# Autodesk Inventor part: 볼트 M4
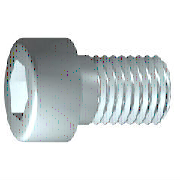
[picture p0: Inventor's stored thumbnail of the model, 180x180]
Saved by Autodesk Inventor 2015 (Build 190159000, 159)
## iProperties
IsCustomPart: 0
Created: 2012-02
Part Number: 볼트 M4
Material: 스테인리스강
Description: 6각 소켓 머리 캡 나사
Document SubType Name: Modeling
Standard: ISO 4762
Designer: mduedu
Standard Revision: Fourth edition 2004-03-01
Standards Organization: ISO
Language: ko-KR
Size Designation: M4 x 12
Categories: <MemberInstance><Categories><Category DisplayName="조임쇠" InternalName="e4da775c-781d-43d5-af7c-5136215cf5a6" Mnemonic="FSTN"><Category DisplayName="볼트" InternalN
Density: 7.75 g/cm^3
Appearance: 반광택
Author: mduedu
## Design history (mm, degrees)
sketch "스케치1"
  geometry: L1 (-1, 0)-(12, 0); L2 (12, 0)-(12, 2); L3 (12, 2)-(1.75, 2); L4 (1.75, 2)-(1.32, 2); L5 (1.32, 2)-(0, 2); L6 (0, 2)-(0, 3.5); L7 (0, 3.5)-(-4, 3.5); L8 (-4, 3.5)-(-4, 1.732); L9 (-4, 1.732)-(-2, 1.732); L10 (-2, 1.732)-(-1, 0); L11 (-7.2, 0)-(15.2, 0) reference; L12 (0, -0.7)-(0, 4.2) reference; L13 (1.75, 2)-(0, 2)
  constraints: 22 end point, 6 parallel, 2 collinear, 2 perpendicular, 1 horizontal, 1 point on line
  dimensions: "d1" = 10.25 distance from line of L3.end L2 (= GEL); "d2" = 0.42952 distance of L4.end L3.end (computed from GAL); "d3" = 4 distance between parallel lines of L8 L6 (= KOH); "d4" = 2 distance of L8.end L9.end (= INTI); "d5" = 60 deg angle of L10 L1; "d6" = 4 diameter of L3 L1 (= GD); "d7" = 4 diameter of L5 L1 (= BDM); "d8" = 3.4641 diameter of L9 L1 (= 1.1547 x SW); "d9" = 7 diameter of L7 L1 (= KOD); "d26" = 12 distance between parallel lines of L12 L2 (= NLG)
revolve "본체" sketch "스케치1" stored, may be unused: angle "d10" = 90 deg
sketch "스케치2"
  geometry: L1 (0, -4.9)-(0, 4.9) reference; L2 (-4.9, 0)-(4.9, 0) reference; L3 (1.732, 0)-(0.866, -1.5); L4 (0.866, -1.5)-(-0.866, -1.5); L5 (-0.866, -1.5)-(-1.732, 0); L6 (-1.732, 0)-(-0.866, 1.5); L7 (-0.866, 1.5)-(0.866, 1.5); L8 (0.866, 1.5)-(1.732, 0); 2 further points
  constraints: 12 end point, 1 coincident, 1 horizontal alignment, 1 point on line, 12 other
extrude "슬롯" join sketch "스케치2" stored distance "d11" = 10; taper "d12" = 0 deg
workplane "Work Plane1"
fillet "Fillet2" dims "d30" = 0.1 (= R)
body "Solid1"
fillet "모깎기1" dims "d17" = 0.4 (= RR)
feature "스레드" dims "d13" = 10.25 (= GEL), "d14" = 0
chamfer "모따기1" distance "d15" = 0.42941 (= -0.5 x SPD + 0.5 x GD); stored, may be unused: second distance "d16" = 0.42941 (= GUL), angle "d27" = 45 deg
other parameters: "GD" = 4 [user parameter; used in 2 equation terms], "NLG" = 12 [user parameter; used in 1 equation term], "GEL" = 10.25 [user parameter; used in 2 equation terms], "KOD" = 7 [user parameter; used in 1 equation term], "KOH" = 4 [user parameter; used in 1 equation term], "INTI" = 2 [user parameter; used in 1 equation term], "GAL" = 0.42941 (= 0.61345 x PTC) [user parameter; used in 1 equation term], "GUL" = 0.42941 (= 0.61345 x PTC) [user parameter; used in 1 equation term], "BDM" = 4 (= NND) [user parameter; used in 1 equation term], "SW" = 3 [user parameter; used in 2 equation terms], "RR" = 0.4 [user parameter; used in 1 equation term], "SPD" = 3.14117 (= NND - 1.2269 x PTC) [user parameter; used in 1 equation term], "d19" = 0, "d28" = 0, "d29" = 0, "R" = 0.1 [user parameter; used in 1 equation term], "TOA" = 30 deg [user parameter], "GD1" = 3.14117 (= THREADDIA - 1.2269 x PTC) [user parameter], "THREADDIA" = 4 [user parameter; used in 1 equation term], "FAWI" = 45 deg [user parameter], "TPU" = 14.28571 (computed from PTC) [user parameter], "PTC" = 0.7 [user parameter; used in 5 equation terms], "NND" = 4 [user parameter; used in 2 equation terms], "E0" = 3.465 (= 1.155 x SW) [user parameter]
